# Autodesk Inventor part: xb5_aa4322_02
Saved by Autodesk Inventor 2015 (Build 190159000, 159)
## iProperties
Created: 2018-05
Part Number: xb5_aa4322_02
Checked By: TraceParts S.A.
Material: Generic
Catalog Web Link: www.traceparts.com
Document SubType Name: Modeling
Designer: TraceParts
Density: 1 g/cm^3
Appearance: Default
Company: TraceParts S.A.
Author: TraceParts
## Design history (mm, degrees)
feature "xb5_aa4322_02.ipt"
body "Solid1"
